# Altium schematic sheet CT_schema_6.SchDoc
size 218 x 258 mm
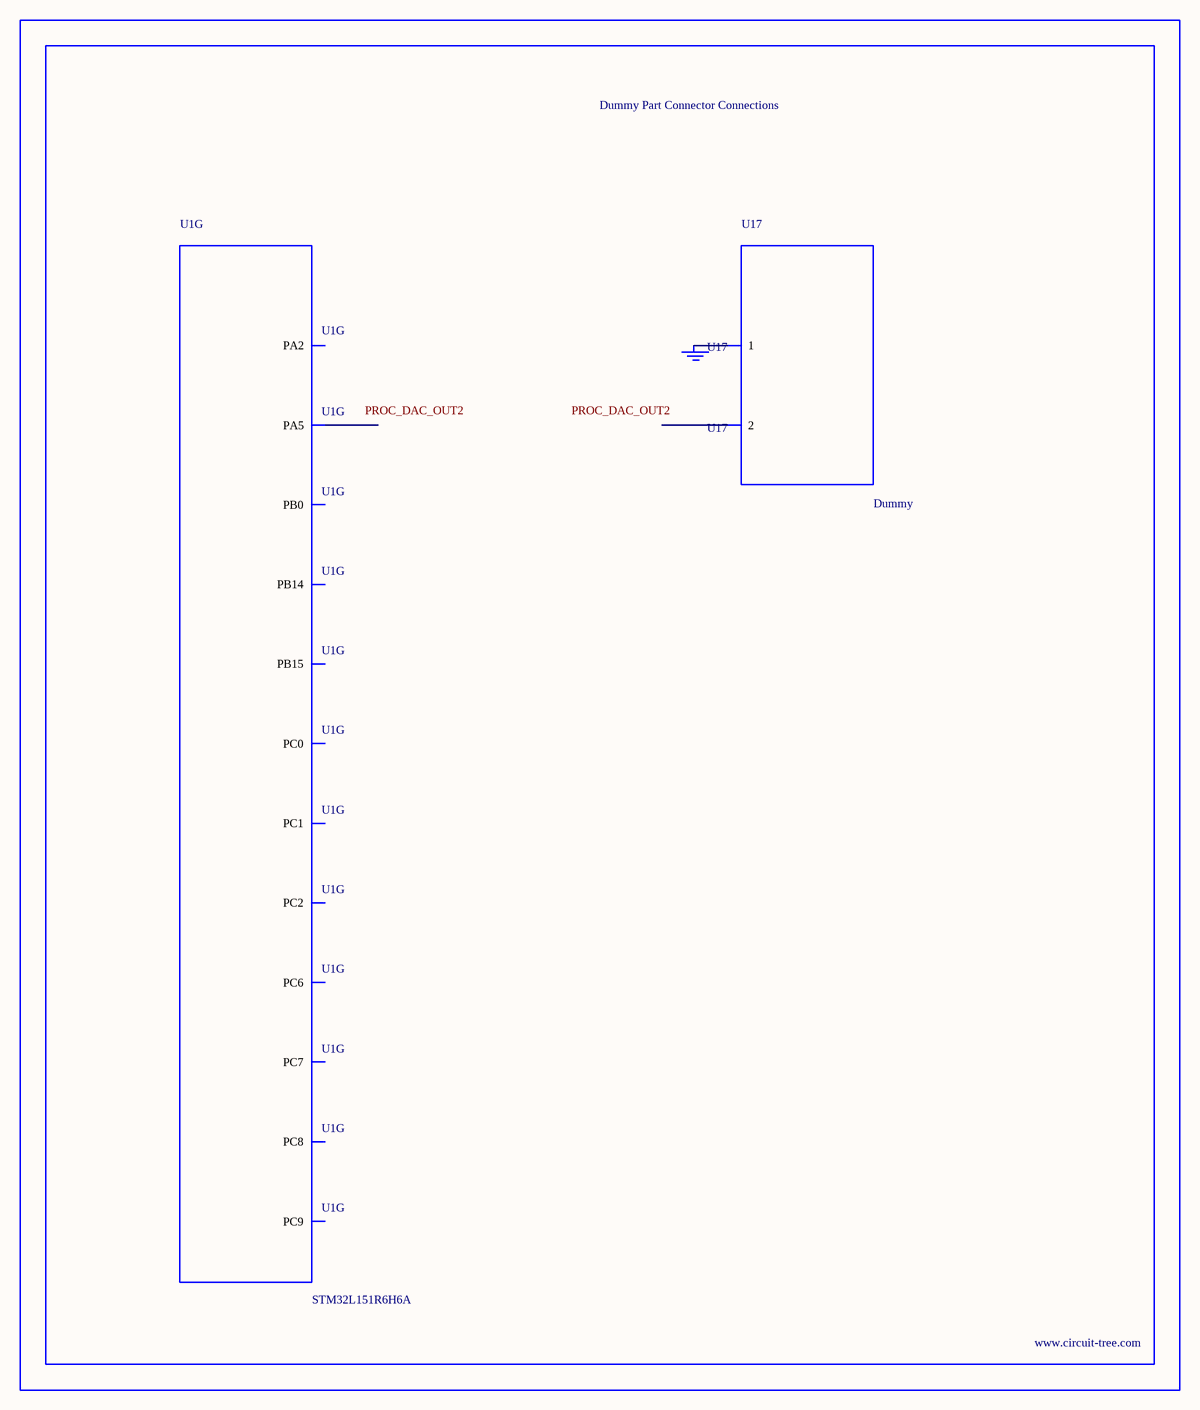
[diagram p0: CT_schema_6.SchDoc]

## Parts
BORDER5  (no value)
GND_INSTANCE_5_0  (no value)
U1  STM32L151R6H6A  [TFBGA64]  (part G of 7)
U17  Dummy  [DUMMY_PACKAGE_165]

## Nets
NetGND_INSTANCE_5_0_0: GND_INSTANCE_5_0.0(GND) U17.1

Not connected (* = marked no-connect by the designer): U1 D8(PC9) E2(PC1) E3(PC0) E7(PC7) E8(PC8) F2(PC2) F3(PA2) F4(PA5) F5(PB0) F6(PC6) F7(PB15) F8(PB14); U17 2

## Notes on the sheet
- Labels drawn without touching a wire or pin: PROC_DAC_OUT2

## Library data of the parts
BORDER5 = BORDER_PAGE5
GND_INSTANCE_5_0 = GND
